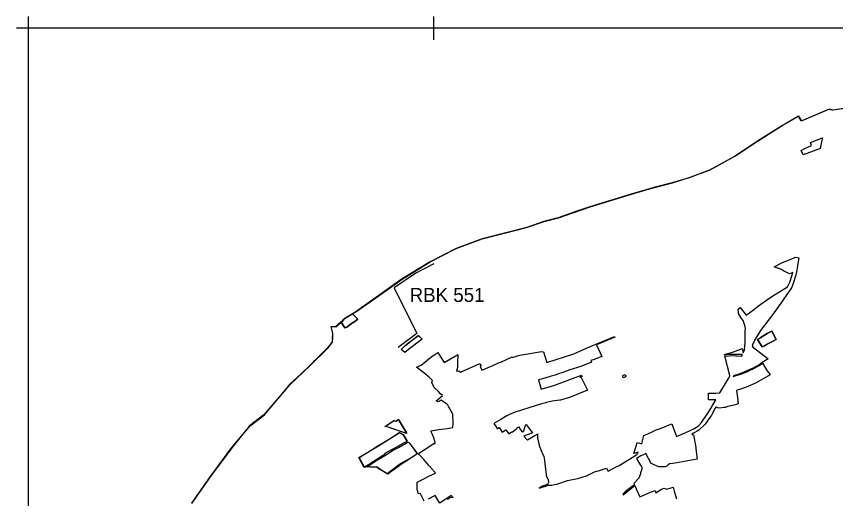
# Model space of a CAD drawing. Extents: x -478490 to -472450, y -1118050 to -1109550.
# Drawn here: x -478490 to -474975, y -1111620 to -1109550 of the extents above; entities that cross this region are included whole.
import ezdxf

# ---------------------------------------------------------------- set-up
doc = ezdxf.new("R2010")
doc.units = 0
for name, color, linetype in [('hranice kú', 7, 'Continuous'), ('Implicitní', 7, 'Continuous'), ('ObPÚ', 7, 'Continuous')]:
    doc.layers.add(name, color=color, linetype=linetype)

msp = doc.modelspace()

# ---------------------------------------------------------------- linework, layer by layer
at = {"layer": 'hranice kú'}
for p, q in [((-475002.4, -1109948.5), (-475022.9, -1109956.5)), ((-474987.2, -1109952.5), (-475002.4, -1109948.5)), ((-474886, -1109937.7), (-474987.2, -1109952.5)), ((-475134, -1109979), (-475207.8, -1110021.5)), ((-475122.4, -1109999.6), (-475134, -1109979)), ((-475022.9, -1109956.5), (-475122.4, -1109999.6)), ((-475207.8, -1110021.5), (-475309.6, -1110086.2)), ((-475309.6, -1110086.2), (-475401.1, -1110146.7)), ((-475408.2, -1110151.3), (-475516.2, -1110210.6)), ((-475401.1, -1110146.7), (-475408.2, -1110151.3)), ((-475516.2, -1110210.6), (-475603.8, -1110242.4)), ((-475675.9, -1110264.8), (-475748.8, -1110283.6)), ((-475603.8, -1110242.4), (-475675.9, -1110264.8)), ((-475774.2, -1110290.1), (-475851.9, -1110313.6)), ((-475748.8, -1110283.6), (-475774.2, -1110290.1)), ((-475851.9, -1110313.6), (-476030.1, -1110367.2)), ((-476030.1, -1110367.2), (-476089.1, -1110387.7)), ((-476089.1, -1110387.7), (-476165.8, -1110414.4)), ((-476226.9, -1110430.6), (-476300.5, -1110456.1)), ((-476165.8, -1110414.4), (-476226.9, -1110430.6)), ((-476390.6, -1110478.9), (-476491.3, -1110505.4)), ((-476300.5, -1110456.1), (-476390.6, -1110478.9)), ((-476491.3, -1110505.4), (-476602.9, -1110545.8)), ((-476602.9, -1110545.8), (-476714.7, -1110603.6)), ((-476714.7, -1110603.6), (-476835.3, -1110677.2)), ((-476835.3, -1110677.2), (-476889.8, -1110715.9)), ((-476889.8, -1110715.9), (-477034.1, -1110817.7)), ((-477047.8, -1110826.2), (-477079.5, -1110846.1)), ((-477034.1, -1110817.7), (-477047.8, -1110826.2)), ((-477098.4, -1110862.6), (-477121, -1110882.3)), ((-477089.2, -1110854.5), (-477098.4, -1110862.6)), ((-477079.5, -1110846.1), (-477089.2, -1110854.5)), ((-477121, -1110882.3), (-477141, -1110882)), ((-477141, -1110882), (-477133.6, -1110911.5)), ((-477134.2, -1110929.3), (-477134.7, -1110947.1)), ((-477133.6, -1110911.5), (-477134.2, -1110929.3)), ((-477155, -1110972.4), (-477210.7, -1111027.9)), ((-477142.3, -1110956.6), (-477155, -1110972.4)), ((-477134.7, -1110947.1), (-477142.3, -1110956.6)), ((-477216.6, -1111033.9), (-477229.4, -1111046.9)), ((-477214.6, -1111031.9), (-477216.6, -1111033.9)), ((-477210.7, -1111027.9), (-477214.6, -1111031.9)), ((-477233.1, -1111050.4), (-477267, -1111082.3)), ((-477229.4, -1111046.9), (-477233.1, -1111050.4)), ((-477267, -1111082.3), (-477317.9, -1111130.4)), ((-477317.9, -1111130.4), (-477350, -1111169.3)), ((-477350, -1111169.3), (-477428.5, -1111260.9)), ((-477428.5, -1111260.9), (-477490.1, -1111308.2)), ((-477490.1, -1111308.2), (-477566.2, -1111401.8)), ((-477566.2, -1111401.8), (-477658.2, -1111526.7)), ((-477658.2, -1111526.7), (-477738.5, -1111640.6))]:
    msp.add_line(p, q, dxfattribs=at)
at = {"layer": 'Implicitní'}
for p, q in [((-478440.1, -1109550.1), (-478440.1, -1109650.1)), ((-478440.1, -1109550.1), (-478440.1, -1109650.1)), ((-478440.1, -1109550.1), (-478440.1, -1109650.1)), ((-478440.1, -1109550.1), (-478440.1, -1109650.1)), ((-478440.1, -1109550.1), (-478440.1, -1109650.1)), ((-478440.1, -1109550.1), (-478440.1, -1109650.1)), ((-476700.1, -1109550.1), (-476700.1, -1109650.1)), ((-476700.1, -1109550.1), (-476700.1, -1109650.1)), ((-476700.1, -1109550.1), (-476700.1, -1109650.1)), ((-476700.1, -1109550.1), (-476700.1, -1109650.1)), ((-476700.1, -1109550.1), (-476700.1, -1109650.1)), ((-476700.1, -1109550.1), (-476700.1, -1109650.1)), ((-478390.1, -1109600.1), (-478490.1, -1109600.1)), ((-478390.1, -1109600.1), (-478490.1, -1109600.1)), ((-478390.1, -1109600.1), (-478490.1, -1109600.1)), ((-478390.1, -1109600.1), (-478490.1, -1109600.1)), ((-478390.1, -1109600.1), (-478490.1, -1109600.1)), ((-476650.1, -1109600.1), (-476750.1, -1109600.1)), ((-476650.1, -1109600.1), (-476750.1, -1109600.1)), ((-476650.1, -1109600.1), (-476750.1, -1109600.1)), ((-476650.1, -1109600.1), (-476750.1, -1109600.1)), ((-476650.1, -1109600.1), (-476750.1, -1109600.1))]:
    msp.add_line(p, q, dxfattribs=at)
msp.add_lwpolyline([(-478440.1, -1118000.1), (-472500.1, -1118000.1), (-472500.1, -1109600.1), (-478440.1, -1109600.1)], close=True, dxfattribs=at)
msp.add_lwpolyline([(-476699, -1110611.9), (-476776, -1110652.7), (-476868.5, -1110715.7), (-476771.5, -1110910.6), (-476852.1, -1110971.5)], dxfattribs=at)
at = {"layer": 'ObPÚ'}
for p, q in [((-476749.5, -1110936), (-476807.4, -1110979.7)), ((-476795.8, -1110942.9), (-476765.1, -1110919.2)), ((-476765.1, -1110919.2), (-476749.5, -1110936)), ((-476838.6, -1110980.4), (-476823.6, -1110964)), ((-476823.6, -1110964), (-476813.4, -1110956.5)), ((-476813.4, -1110956.5), (-476795.8, -1110942.9)), ((-476823.5, -1110992.3), (-476838.6, -1110980.4)), ((-476807.4, -1110979.7), (-476823.5, -1110992.3)), ((-476909, -1111310.7), (-476870.1, -1111284.8)), ((-476870.1, -1111284.8), (-476863.3, -1111287.6)), ((-476863.3, -1111287.6), (-476852.1, -1111280.5)), ((-476852.1, -1111280.5), (-476817.4, -1111337.3)), ((-476900.7, -1111312.2), (-476909, -1111310.7)), ((-476891.2, -1111315.2), (-476900.7, -1111312.2)), ((-476878.5, -1111319.2), (-476891.2, -1111315.2)), ((-476816.7, -1111340.2), (-476878.5, -1111319.2)), ((-476817.4, -1111337.3), (-476816.7, -1111340.2))]:
    msp.add_line(p, q, dxfattribs=at)
for points in [[(-477737.4, -1111639.5), (-477657.3, -1111525.4), (-477565.5, -1111400.8), (-477486.9, -1111307), (-477426, -1111261.1), (-477348, -1111168.5), (-477315.2, -1111130.2), (-477231.4, -1111050.6), (-477154.2, -1110973.6), (-477134.2, -1110948.8), (-477133.2, -1110930.3), (-477132.1, -1110911.9), (-477138.9, -1110881.3), (-477119.7, -1110882.7), (-477097.2, -1110862.7), (-477080.6, -1110886.8), (-477072.5, -1110883.8), (-477045.9, -1110863.6), (-477043.9, -1110864.1), (-477025.3, -1110849.6), (-477043.5, -1110830.7), (-477047.5, -1110826.1), (-477033.7, -1110818.2), (-476934, -1110747.9), (-476834.4, -1110677.8), (-476714.6, -1110603.8), (-476602.9, -1110545.9), (-476491.3, -1110505.5), (-476390.2, -1110478.8), (-476300.7, -1110455.7), (-476225.2, -1110430.7), (-476164.4, -1110414.7), (-476028.4, -1110367.7), (-475850.6, -1110313.7), (-475773.2, -1110290.1), (-475675.4, -1110264.4), (-475603.9, -1110241.6), (-475515.6, -1110210.1), (-475407.7, -1110150.6), (-475310.4, -1110085.4), (-475208.2, -1110020.8), (-475134, -1109978.4), (-475121.9, -1109999.1), (-475023.6, -1109956.4), (-475002.8, -1109948.9), (-474998, -1109949.5), (-474990.2, -1109950.6), (-474989.1, -1109950.8), (-474987.5, -1109951), (-474886.4, -1109937.2)], [(-475031.6, -1110070.7), (-475035.2, -1110088.3), (-475041.6, -1110117.3), (-475071, -1110128.2), (-475113.6, -1110143.8), (-475122.4, -1110125.3), (-475107.2, -1110116.9), (-475078.7, -1110104.2), (-475082.7, -1110091.8), (-475031.6, -1110070.7)], [(-475148.1, -1110584.1), (-475132.8, -1110586.1), (-475134.1, -1110594.3), (-475139.6, -1110629.2), (-475141.4, -1110640.6), (-475147, -1110664.5), (-475156.6, -1110696.8), (-475164.7, -1110715.7), (-475219.8, -1110795.7), (-475246.4, -1110830.8), (-475297.9, -1110899.1), (-475322.5, -1110939.2), (-475323.4, -1110941.1), (-475326.2, -1110947.8), (-475332.4, -1110960.1), (-475329.7, -1110962.2), (-475332.8, -1110966.5), (-475264.7, -1111020.3), (-475289.6, -1111035.6), (-475304.6, -1111046.6), (-475313.5, -1111051.8), (-475327.3, -1111059.4), (-475332.9, -1111062), (-475368.8, -1111077.8), (-475390.2, -1111085.2), (-475413.5, -1111093), (-475413.9, -1111095.5), (-475414.6, -1111096.5), (-475396.8, -1111090.7), (-475381.9, -1111085.4), (-475368.1, -1111080.4), (-475352.2, -1111073.9), (-475342, -1111069.3), (-475326, -1111062.1), (-475313, -1111054.8), (-475303.1, -1111049.2), (-475289.4, -1111039.2), (-475271.1, -1111067.1), (-475256.4, -1111089.3), (-475305.6, -1111116.7), (-475319, -1111124.5), (-475352.1, -1111139), (-475379.3, -1111149.1), (-475393.3, -1111153.4), (-475400.3, -1111156), (-475396.5, -1111185.4), (-475392.7, -1111213), (-475404.3, -1111216.8), (-475436.9, -1111225.3), (-475448.5, -1111228.4), (-475454.5, -1111229.6), (-475463.7, -1111230.8), (-475472.8, -1111231.1), (-475479.9, -1111230.5), (-475488.1, -1111228), (-475488.8, -1111227.8), (-475491.2, -1111232.3), (-475508.3, -1111261.2), (-475522.4, -1111282.1), (-475534.8, -1111300.6), (-475562.6, -1111326.6), (-475569.6, -1111330.7), (-475585.2, -1111339.6), (-475592.6, -1111343.6), (-475588.6, -1111346.6), (-475584.2, -1111346.5), (-475575.5, -1111400.7), (-475574.6, -1111407), (-475568.6, -1111450.4), (-475601.1, -1111456.6), (-475624.5, -1111461.2), (-475654.2, -1111466.4), (-475684.3, -1111471.3), (-475687.2, -1111470.6), (-475693.7, -1111474.8), (-475699, -1111480.1), (-475705.7, -1111483.9), (-475709.8, -1111483.9), (-475733.4, -1111483.1), (-475767, -1111469.8), (-475790, -1111426.6), (-475799.8, -1111431.5), (-475804, -1111433.4), (-475810.7, -1111436.7), (-475829.7, -1111448), (-475814.9, -1111472), (-475806.3, -1111484.8), (-475806.3, -1111493.2), (-475811.6, -1111509.7), (-475812.7, -1111512.9), (-475812.9, -1111513.5), (-475819.1, -1111532.4), (-475841.2, -1111555.7), (-475838.5, -1111560.3), (-475845.9, -1111566.1), (-475877.4, -1111590.5)], [(-475218.2, -1110632.5), (-475219.5, -1110631.9), (-475238.7, -1110624.8), (-475202.4, -1110607.1), (-475184, -1110598.8), (-475149.9, -1110584.6), (-475148.1, -1110584.1)], [(-476080.7, -1111533.9), (-476044.6, -1111522.8), (-476009.2, -1111505.3), (-476006, -1111504.3), (-476001.7, -1111502.9), (-475992.1, -1111500.1), (-475958.5, -1111489.8), (-475951, -1111502.6), (-475913.8, -1111482.5), (-475907.2, -1111479.6), (-475903.4, -1111477.7), (-475840.3, -1111439.7), (-475827.1, -1111429.9), (-475826.5, -1111427.2), (-475822.6, -1111420.1), (-475841.5, -1111426.4), (-475831.2, -1111395.6), (-475825.9, -1111379.1), (-475807.2, -1111385.2), (-475804.9, -1111377.5), (-475797.7, -1111349), (-475791.1, -1111346.2), (-475768.3, -1111335.9), (-475744.5, -1111325.5), (-475728.4, -1111319.2), (-475712.4, -1111312.7), (-475696.6, -1111306.6), (-475678, -1111299.1), (-475661.4, -1111342.5), (-475657.5, -1111352.7), (-475617.2, -1111336.5), (-475580, -1111319.1), (-475562.6, -1111305.8), (-475549.8, -1111292.6), (-475525.8, -1111258.2), (-475508.2, -1111228.6), (-475505.8, -1111225), (-475499.2, -1111213), (-475489.2, -1111195.3), (-475521.1, -1111196.7), (-475521.1, -1111167.4), (-475509.5, -1111167.4), (-475488.5, -1111167.2), (-475472.4, -1111166.6), (-475447.9, -1111126.5), (-475434.6, -1111104.4), (-475428.9, -1111094.7), (-475429.3, -1111091.8), (-475450.3, -1111008.5), (-475431.9, -1111006.9), (-475417.8, -1111006.3), (-475403.1, -1111007.2), (-475398.3, -1111007.7), (-475379.8, -1111008.2), (-475378.3, -1111008.3), (-475374.8, -1111001.4), (-475389.4, -1111001.4), (-475396.2, -1111001.5), (-475432.4, -1111001.7), (-475451.6, -1111003.6), (-475452.3, -1111000.8), (-475417.3, -1110991.5), (-475392.6, -1110982.3), (-475375.7, -1110975.9), (-475373.5, -1110983.9), (-475371.1, -1110993.9), (-475364.9, -1110979.2), (-475366.7, -1110978.5), (-475362.9, -1110952.1), (-475362.8, -1110931.7), (-475362.6, -1110916.2), (-475362.9, -1110905.9), (-475363, -1110901.2), (-475363, -1110898.2), (-475361.8, -1110890.2), (-475364.3, -1110877.5), (-475372.3, -1110855.4), (-475379.1, -1110847.3), (-475391.9, -1110824.9), (-475393.8, -1110806.5), (-475383.9, -1110799.9), (-475359.1, -1110832.8), (-475343.3, -1110821.2), (-475301.6, -1110790.1), (-475295.5, -1110785.5), (-475271.4, -1110767.5), (-475248.6, -1110752.7), (-475181.1, -1110710.8), (-475171.1, -1110690.7), (-475163.2, -1110663.4), (-475159.1, -1110649.7), (-475173.1, -1110654.9), (-475181, -1110650.7), (-475198.3, -1110641.7), (-475207.7, -1110637.2), (-475218.2, -1110632.5)], [(-477047.5, -1110826.1), (-477043.5, -1110830.7), (-477025.3, -1110849.6), (-477043.9, -1110864.1), (-477045.9, -1110863.6), (-477072.5, -1110883.8), (-477080.6, -1110886.8), (-477097.2, -1110862.7), (-477088.2, -1110854.8), (-477078.9, -1110846), (-477062.1, -1110835), (-477047.5, -1110826.1)], [(-476765.5, -1110919.5), (-476749.7, -1110936.3), (-476807.4, -1110980.3), (-476823.5, -1110992.5), (-476838.5, -1110980.6), (-476823.2, -1110963.8), (-476813.4, -1110956.1), (-476796, -1110942.8), (-476765.5, -1110919.5)], [(-476755.5, -1111599), (-476755.8, -1111598), (-476764.4, -1111599.6), (-476770.5, -1111580.2), (-476771, -1111565.2), (-476770.2, -1111549.7), (-476741.8, -1111534.8), (-476732, -1111529.7), (-476696.8, -1111511.7), (-476692.5, -1111509.2), (-476710.4, -1111489.4), (-476712.4, -1111487.1), (-476720, -1111478.1), (-476742.3, -1111451.6), (-476761.2, -1111430.1), (-476764.4, -1111426.4), (-476763, -1111425.6), (-476729.7, -1111402.9), (-476697.2, -1111382.4), (-476694.7, -1111386.2), (-476693.6, -1111380.2), (-476694.2, -1111372.8), (-476699.2, -1111358.8), (-476706, -1111342.3), (-476712.2, -1111331.2), (-476708.5, -1111329.6), (-476702.9, -1111327.4), (-476678.2, -1111323.1), (-476641.2, -1111318.6), (-476634.7, -1111317.8), (-476617.1, -1111314.8), (-476616.1, -1111297.4), (-476616.8, -1111259.6), (-476619.4, -1111254.6), (-476636.7, -1111224.2), (-476638.2, -1111219.2), (-476639.6, -1111217.9), (-476648.1, -1111211.8), (-476657.2, -1111205.2), (-476667.7, -1111197.8), (-476668.1, -1111197.6), (-476680.6, -1111204.3), (-476688.9, -1111200.3), (-476683.5, -1111195.6), (-476662.2, -1111177.8), (-476669.9, -1111169.8), (-476680.8, -1111158.9), (-476694.9, -1111146.1), (-476702.3, -1111134.6), (-476708.2, -1111120.9), (-476704.6, -1111113.1), (-476707.2, -1111110.4), (-476710.6, -1111106.8), (-476721, -1111096.9), (-476747.1, -1111075.5), (-476773.1, -1111056.3), (-476753.8, -1111047.8), (-476712.6, -1111014.6), (-476702.4, -1111006.3), (-476694.3, -1111001.1), (-476681.6, -1110992.9), (-476666.8, -1111016), (-476654.4, -1111035.6), (-476600.8, -1111004.3), (-476595.3, -1111001.9), (-476597.5, -1111034), (-476597.6, -1111049.7), (-476597.4, -1111057.5), (-476602.2, -1111073.2), (-476591.8, -1111071.3), (-476584.8, -1111077.5), (-476501, -1111039.4), (-476495.6, -1111050.2), (-476500.4, -1111052.6), (-476492.4, -1111068.6), (-476455.9, -1111052.7), (-476446, -1111048.3), (-476423.8, -1111038.9), (-476408.7, -1111032.4), (-476362.8, -1111011.5), (-476363.1, -1111014.2), (-476329.8, -1111004.9), (-476321.4, -1111003.2), (-476295.6, -1110998.1), (-476262.7, -1110992.2), (-476245.3, -1110989.6), (-476239, -1110988.4), (-476229.4, -1110989.3), (-476228.4, -1110989.3), (-476213.9, -1111036.2), (-476097.8, -1110998.2), (-476044, -1110974.6), (-476040.4, -1110973.1), (-475923.9, -1110923.8), (-475922.9, -1110926.6), (-476001.2, -1110960.1)], [(-476001.2, -1110960.1), (-475978.5, -1111010.4), (-476010.9, -1111022.5), (-476024.9, -1111027.8), (-476022.1, -1111034.1), (-476068.7, -1111052.3), (-476114.9, -1111067.7), (-476138.6, -1111076), (-476141.9, -1111077.2), (-476168.5, -1111086.4), (-476178.6, -1111089.9), (-476195.4, -1111094.7), (-476223, -1111102.6), (-476238.7, -1111107), (-476249.6, -1111110.1), (-476237.8, -1111150.3), (-476184.5, -1111134.3), (-476103.8, -1111104.7), (-476065.3, -1111090.1), (-476062.5, -1111096.4), (-476072.5, -1111099), (-476067.4, -1111100.8), (-476057.5, -1111119.9), (-476052.6, -1111129.4), (-476039.5, -1111154.8), (-476078.4, -1111169.8), (-476117, -1111185.5), (-476155.8, -1111197), (-476158.1, -1111197.3), (-476191.7, -1111201.9), (-476214.9, -1111207.7), (-476217.9, -1111208.5), (-476236.6, -1111213.2), (-476323, -1111239.7), (-476350.1, -1111249), (-476375, -1111259), (-476385.9, -1111264.8), (-476392.2, -1111269.7), (-476411, -1111280.8), (-476441.4, -1111298.3), (-476428.9, -1111316.6), (-476426.7, -1111320.2), (-476425.5, -1111319.4), (-476418.1, -1111314.4), (-476406.1, -1111334.8), (-476390, -1111324.6), (-476377.8, -1111342), (-476366.1, -1111333.4), (-476364.4, -1111335.6), (-476361.5, -1111333.8), (-476342.9, -1111319.2), (-476343.8, -1111317.9), (-476335.7, -1111311.8), (-476321.2, -1111332.1), (-476318.9, -1111334.9), (-476313, -1111328.6), (-476309.8, -1111318.6), (-476305.3, -1111306.9), (-476302.5, -1111302), (-476275.6, -1111337.5), (-476313.2, -1111352.2), (-476300.2, -1111365.6), (-476297.2, -1111368.2), (-476265.8, -1111348.7), (-476253.2, -1111341.5), (-476254.2, -1111345.1), (-476254.1, -1111360.3), (-476252.9, -1111365.5), (-476247.1, -1111391.9), (-476235, -1111420.9), (-476233.9, -1111423.6), (-476227.1, -1111439.9), (-476225.4, -1111444.4), (-476220, -1111494.3), (-476219.8, -1111496.3), (-476219.6, -1111498.6), (-476218.9, -1111504.2), (-476216.5, -1111519.8), (-476214.9, -1111524.1), (-476208.9, -1111538.8), (-476206.5, -1111547), (-476206.4, -1111550.3), (-476211.4, -1111559.3), (-476232.4, -1111567.1), (-476247.2, -1111575.1), (-476229.9, -1111569.6), (-476218.5, -1111566.3), (-476210.1, -1111562.7), (-476205.2, -1111562.3), (-476193.3, -1111561.9), (-476181.7, -1111559.9), (-476167.6, -1111555.9), (-476126.1, -1111541.6), (-476097.4, -1111535.9), (-476082.4, -1111534.1), (-476080.7, -1111533.9)], [(-475878.6, -1111087.3), (-475875.6, -1111094.7), (-475876.6, -1111095.2), (-475876.2, -1111096.1), (-475875.8, -1111097), (-475885.9, -1111101.2), (-475886.3, -1111100.2), (-475888.6, -1111093.7), (-475887, -1111093.1), (-475887.8, -1111091.1), (-475878.6, -1111087.3)], [(-476851.2, -1111280.9), (-476816.7, -1111337.6), (-476815.9, -1111340.5), (-476877.8, -1111319.3), (-476890.3, -1111315.3), (-476899.7, -1111312.3), (-476908, -1111310.6), (-476869, -1111284.9), (-476862.3, -1111287.4), (-476851.2, -1111280.9)], [(-476845.8, -1111336.8), (-476833.2, -1111343.1), (-476830.3, -1111345.2), (-476814.1, -1111373.4), (-476829.7, -1111382.6), (-476871.8, -1111406), (-476907.9, -1111425.4), (-476911.4, -1111431), (-476914.7, -1111433.2), (-476935, -1111446.2), (-476979.5, -1111474.5), (-476996.8, -1111485.2), (-477019.2, -1111443.1), (-476956.1, -1111404.4), (-476941.7, -1111395.5), (-476928.8, -1111387.7), (-476892.8, -1111365.7), (-476851.6, -1111340.4), (-476845.8, -1111336.8)], [(-476810.1, -1111378.3), (-476805.9, -1111379.4), (-476804.7, -1111380.3), (-476803.4, -1111382.1), (-476792.3, -1111397.6), (-476773.7, -1111423.2), (-476770.2, -1111428.1), (-476787.4, -1111439.3), (-476804.2, -1111450.6), (-476823.1, -1111463.3), (-476837.9, -1111472.8), (-476847.1, -1111479.5), (-476850.6, -1111481.9), (-476879.3, -1111502.4), (-476896.2, -1111514.4), (-476899, -1111514.2), (-476930.7, -1111494), (-476942.5, -1111485.1), (-476965.9, -1111485.2), (-476984.4, -1111483.5), (-476947.9, -1111458.3), (-476916.7, -1111438.9), (-476890.7, -1111423.1), (-476880.5, -1111416.9), (-476873.4, -1111412.5), (-476851.1, -1111400.2), (-476833, -1111390.3), (-476824.8, -1111385.7), (-476813, -1111378.7), (-476810.1, -1111378.3)], [(-475877.4, -1111590.5), (-475888.6, -1111601.4), (-475886, -1111604.2), (-475836, -1111564.4), (-475833.6, -1111570.2), (-475830.2, -1111577.9), (-475814.8, -1111612), (-475761.7, -1111589.4), (-475749.3, -1111584.9), (-475746.8, -1111594.7), (-475738, -1111589.5), (-475721.7, -1111579.9), (-475710.7, -1111575.7), (-475699.7, -1111579.1), (-475672.1, -1111571.2), (-475667.3, -1111587.5), (-475657.2, -1111621.4)], [(-476740.9, -1111630.8), (-476754.6, -1111602.9), (-476755.5, -1111599)], [(-476639.8, -1111622.5), (-476624.6, -1111614.3), (-476615.7, -1111614.8), (-476624, -1111606.8), (-476672.6, -1111638.9), (-476693.6, -1111607.2), (-476722.7, -1111621.8)]]:
    msp.add_lwpolyline(points, dxfattribs=at)
for points in [[(-475309.6, -1110937.3), (-475298.3, -1110930.6), (-475298.9, -1110929.2), (-475268.3, -1110911.9), (-475249.1, -1110901.1), (-475230.6, -1110937.3), (-475253.9, -1110949.2), (-475272, -1110958.9), (-475280.6, -1110963.6), (-475290, -1110968.6)], [(-475309.6, -1110937.3), (-475290, -1110968.6), (-475280.6, -1110963.6), (-475272, -1110958.9), (-475253.9, -1110949.2), (-475230.6, -1110937.3), (-475249.1, -1110901.1), (-475268.3, -1110911.9), (-475298.9, -1110929.2), (-475298.3, -1110930.6)], [(-476847.1, -1111336.5), (-476831.3, -1111345), (-476814.5, -1111373.1), (-476813.5, -1111378.5), (-476810.5, -1111378.2), (-476806.2, -1111379.8), (-476803.9, -1111382.7), (-476792.3, -1111397.2), (-476773, -1111422.4), (-476769.2, -1111426.6), (-476786.4, -1111438.9), (-476824.6, -1111461), (-476839.5, -1111469.7), (-476846, -1111473.3), (-476899.9, -1111514.2), (-476935.6, -1111492.1), (-476945.3, -1111484.7), (-476973.5, -1111485.2), (-476986, -1111484.2), (-476998.5, -1111486), (-477020.9, -1111443.5), (-476943, -1111397.1), (-476931.4, -1111390.2), (-476893.5, -1111366.1), (-476853.3, -1111340.3)]]:
    msp.add_lwpolyline(points, close=True, dxfattribs=at)

# ---------------------------------------------------------------- texts
at = {"layer": 'Implicitní'}
msp.add_text('RBK 551', height=60, dxfattribs=at).set_placement((-476802.8, -1110775.8))

doc.saveas('drawing.dxf')
